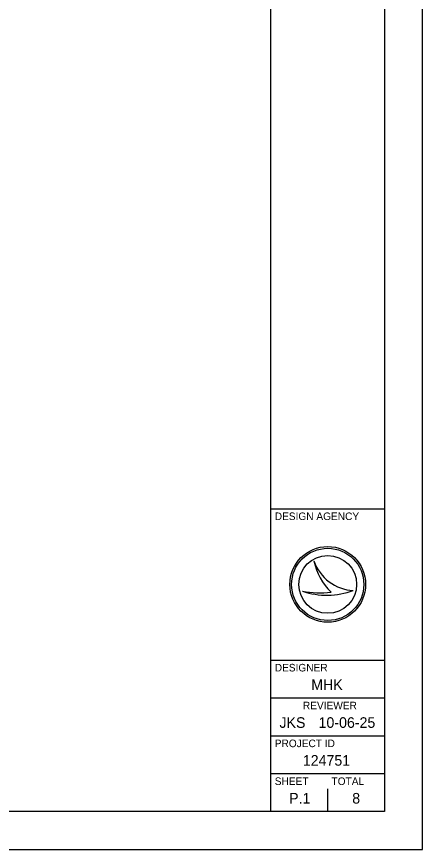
# Model space of a CAD drawing. Extents: x 0 to 34, y 0 to 22.
# Drawn here: x 28.64 to 34, y 0 to 11 of the extents above; entities that cross this region are included whole.
import ezdxf

# ---------------------------------------------------------------- set-up
doc = ezdxf.new("R2010")
doc.units = 0
for name, color, linetype in [('SH_Border', 7, 'Continuous'), ('SH_Cut_Line', 7, 'Continuous'), ('SH_Data', 7, 'Continuous')]:
    doc.layers.add(name, color=color, linetype=linetype)

msp = doc.modelspace()

# ---------------------------------------------------------------- linework, layer by layer
at = {"layer": 'SH_Border'}
for p, q in [((32, 0.5), (32, 21.5)), ((32, 4.5), (33.5, 4.5)), ((32, 2.5), (33.5, 2.5)), ((32, 2), (33.5, 2)), ((32, 1.5), (33.5, 1.5)), ((32, 1), (33.5, 1))]:
    msp.add_line(p, q, dxfattribs=at)
msp.add_lwpolyline([(1.5, 21.5), (33.5, 21.5), (33.5, 0.5), (1.5, 0.5)], close=True, dxfattribs=at)
at = {"layer": 'SH_Cut_Line'}
msp.add_lwpolyline([(0, 0), (34, 0), (34, 22), (0, 22)], close=True, dxfattribs=at)
at = {"layer": 'SH_Data'}
for p, q in [((32.567, 3.81), (32.567, 3.81)), ((32.75, 3.5), (32.75, 3.5)), ((33.087, 3.419), (33.087, 3.419)), ((32.417, 3.41), (32.417, 3.41)), ((32.75, 0.5), (32.75, 0.8)), ((32.375, 0.675), (32.375, 0.675))]:
    msp.add_line(p, q, dxfattribs=at)
for radius in [0.5, 0.477, 0.477, 0.382]:
    msp.add_circle((32.75, 3.5), radius, dxfattribs=at)
for centre, radius, start, end in [((33.116, 3.998), 0.58, 198.9257, 198.9319), ((33.347, 3.97), 0.796, 191.6379, 191.6421), ((33.116, 3.998), 0.58, 198.9319, 267.1657), ((33.347, 3.97), 0.796, 191.6421, 226.0947), ((32.739, 4.37), 1.013, 251.4576, 290.0832), ((32.648, 4.654), 1.266, 259.4964, 259.4995), ((32.739, 4.37), 1.013, 251.4527, 251.4576), ((32.648, 4.654), 1.266, 259.4995, 276.6672)]:
    msp.add_arc(centre, radius, start, end, dxfattribs=at)

# ---------------------------------------------------------------- texts
for s, height, p in [('DESIGN AGENCY', 0.1, (32.05, 4.35)), ('DESIGNER', 0.1, (32.05, 2.35)), ('MHK', 0.14, (32.532, 2.105)), ('REVIEWER', 0.1, (32.422, 1.85)), ('JKS', 0.14, (32.112, 1.605)), ('10-06-25', 0.14, (32.629, 1.605)), ('PROJECT ID', 0.1, (32.05, 1.35)), ('124751', 0.14, (32.421, 1.105)), ('SHEET', 0.1, (32.05, 0.85)), ('TOTAL', 0.1, (32.8, 0.85)), ('P.1', 0.14, (32.24, 0.605)), ('8', 0.14, (33.074, 0.605))]:
    msp.add_text(s, height=height, dxfattribs=at).set_placement(p)

doc.saveas('drawing.dxf')
